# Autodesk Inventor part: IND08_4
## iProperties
Created: 2006-01
Part Number: IND08_4
Document SubType Name: Modeling
Designer: DES
Author: DES
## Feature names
1. Extrude Block
2. Spotface Extrude Half [Extrusion]
3. Revolve Cav Form
